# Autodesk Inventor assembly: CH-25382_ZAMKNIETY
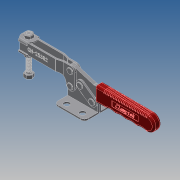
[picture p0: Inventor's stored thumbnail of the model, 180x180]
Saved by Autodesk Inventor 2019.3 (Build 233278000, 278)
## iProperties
Company: Î¢ÈíÖÐ¹ú
Created: 2012-09
Part Number: CH-25382_ZAMKNIETY
Material: Ogólny
Description: STEP AP203
Document SubType Name: Assembly
Designer: CADENGINEERING4
Stock Number: DOCISKI POZIOME
Sending System: SolidWorks 2010
Preprocessor: SwSTEP 2.0
Title: CH-25382.STEP
Author: Î¢ÈíÓÃ»§
Revision Number: ÈÎºÎ
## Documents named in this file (10)
- E:\STRONA\Horizontal toggle clamp\CH-25382\CH-25382_ZAMKNIETY.iam
- E:\STRONA\Horizontal toggle clamp\CH-25382\25382-04.ipt
- E:\STRONA\Horizontal toggle clamp\CH-25382\25382-05.ipt
- E:\STRONA\Horizontal toggle clamp\CH-25382\25382-02.ipt
- E:\STRONA\Horizontal toggle clamp\CH-25382\FW380.ipt
- E:\STRONA\Horizontal toggle clamp\CH-25382\M8.ipt
- E:\STRONA\Horizontal toggle clamp\CH-25382\25382-03.ipt
- E:\STRONA\Horizontal toggle clamp\CH-25382\086512.ipt
- E:\STRONA\Horizontal toggle clamp\CH-25382\01.ipt
- E:\STRONA\Horizontal toggle clamp\CH-25382\25382-01.ipt
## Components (15 placed, 15 different names)
1. 25382-04_1 — Zestawiające:13, Zestawiające:16, Zestawiające:17, Zestawiające:19, Zestawiające:24, Zestawiające:25, Zestawiające:26, Zestawiające:27
2. 25382-05_2 — Zestawiające:22, Zestawiające:23
3. 25382-02_3 — Równoległe:2, Zestawiające:7, Zestawiające:9, Zestawiające:12, Zestawiające:20, Zestawiające:21, Zestawiające:23, Zestawiające:28, Zestawiające:29, Zestawiające:30
4. FW380_4 — Równoległe:3, Zestawiające:8, Zestawiające:9, Zestawiające:11
5. M8_5 — Zestawiające:10, Zestawiające:11
6. 25382-05_6 — Zestawiające:29, Zestawiające:30
7. 25382-03_7 — Zestawiające:1, Zestawiające:2, Zestawiające:3, Zestawiające:24, Zestawiające:25, Zestawiające:28, Przejściowe:1
8. 086512_8 — Równoległe:1, Zestawiające:4, Zestawiające:5, Zestawiające:8, Zestawiające:10, Zestawiające:12
9. 01_9 — Zestawiające:1, Zestawiające:2, Zestawiające:3
10. 25382-05_10 — Zestawiające:26, Zestawiające:27
11. 25382-01_11 — Zestawiające:13, Zestawiające:14, Zestawiające:15, Zestawiające:16, Zestawiające:18, Zestawiające:20, Zestawiające:21, Zestawiające:22, Przejściowe:1
12. 25382-04_12 — Zestawiające:14, Zestawiające:15, Zestawiające:17
13. FW380_13 — Równoległe:2, Równoległe:3, Zestawiające:5, Zestawiające:6, Zestawiające:7
14. 25382-05_14 — Zestawiające:18, Zestawiające:19
15. M8_15 — Równoległe:1, Zestawiające:4, Zestawiające:6
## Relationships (34: Mate 30, Flush 3, Transitional 1)
- Równoległe:1 [Flush]: 086512_8 ↔ M8_15
- Równoległe:2 [Flush]: 25382-02_3 ↔ FW380_13
- Równoległe:3 [Flush]: FW380_4 ↔ FW380_13
- Zestawiające:1 [Mate]: 25382-03_7 ↔ 01_9
- Zestawiające:2 [Mate]: 25382-03_7 ↔ 01_9
- Zestawiające:3 [Mate]: 25382-03_7 ↔ 01_9
- Zestawiające:4 [Mate]: 086512_8 ↔ M8_15
- Zestawiające:5 [Mate]: 086512_8 ↔ FW380_13
- Zestawiające:6 [Mate]: FW380_13 ↔ M8_15
- Zestawiające:7 [Mate]: 25382-02_3 ↔ FW380_13
- Zestawiające:8 [Mate]: FW380_4 ↔ 086512_8
- Zestawiające:9 [Mate]: 25382-02_3 ↔ FW380_4
- Zestawiające:10 [Mate]: M8_5 ↔ 086512_8
- Zestawiające:11 [Mate]: FW380_4 ↔ M8_5
- Zestawiające:12 [Mate]: 25382-02_3 ↔ 086512_8
- Zestawiające:13 [Mate]: 25382-04_1 ↔ 25382-01_11
- Zestawiające:14 [Mate]: 25382-01_11 ↔ 25382-04_12
- Zestawiające:15 [Mate]: 25382-01_11 ↔ 25382-04_12
- Zestawiające:16 [Mate]: 25382-04_1 ↔ 25382-01_11
- Zestawiające:17 [Mate]: 25382-04_1 ↔ 25382-04_12
- Zestawiające:18 [Mate]: 25382-01_11 ↔ 25382-05_14
- Zestawiające:19 [Mate]: 25382-04_1 ↔ 25382-05_14
- Zestawiające:20 [Mate]: 25382-02_3 ↔ 25382-01_11
- Zestawiające:21 [Mate]: 25382-02_3 ↔ 25382-01_11
- Zestawiające:22 [Mate]: 25382-05_2 ↔ 25382-01_11
- Zestawiające:23 [Mate]: 25382-05_2 ↔ 25382-02_3
- Zestawiające:24 [Mate]: 25382-04_1 ↔ 25382-03_7
- Zestawiające:25 [Mate]: 25382-04_1 ↔ 25382-03_7
- Zestawiające:26 [Mate]: 25382-04_1 ↔ 25382-05_10
- Zestawiające:27 [Mate]: 25382-04_1 ↔ 25382-05_10
- Zestawiające:28 [Mate]: 25382-02_3 ↔ 25382-03_7
- Zestawiające:29 [Mate]: 25382-02_3 ↔ 25382-05_6
- Zestawiające:30 [Mate]: 25382-02_3 ↔ 25382-05_6
- Przejściowe:1 [Transitional]: 25382-03_7 ↔ 25382-01_11
